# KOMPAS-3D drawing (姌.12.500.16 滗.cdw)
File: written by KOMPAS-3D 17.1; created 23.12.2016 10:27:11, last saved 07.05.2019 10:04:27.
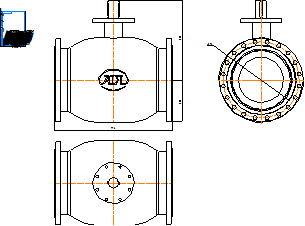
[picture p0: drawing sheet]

Sheet 1: A4, portrait

Title block, sheet 1: name: КШ.12.500.16 фф; material: Внимание! Данный продукт является объектом авторского права ООО «Торговый Дом АДЛ». / Запрещается изменение, копирование, распространение / (в том числе путем копирования на другие сайты и ресурсы в Интернете) / или любое иное использование информации и объектов без предварительного / согласия правообладателя (ООО «Торговый Дом АДЛ»).; sheets: 1; organisation: ООО "Торговый дом АДЛ"; sheet format: A4; stored path: C:\Users\tra\Desktop\2д чертежи\Шаровые краны БИВАЛ\КШ_Бивал_серия_11_12\KOMPAS_2D\КШ.12.500.16 фф.cdw

Views: Вид 1, Проекционный вид 3
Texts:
  Klimkovich
  ADL
Dimensions and other numbers on the sheet: 996; 673; 355; 1:1; 1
